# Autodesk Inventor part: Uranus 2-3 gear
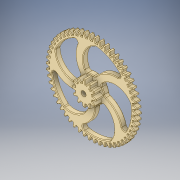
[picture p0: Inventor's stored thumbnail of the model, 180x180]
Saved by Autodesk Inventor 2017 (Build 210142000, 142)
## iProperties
Created: 2016-05
Part Number: Uranus 2-3 gear
Material: Generic
Document SubType Name: Modeling
Designer: Stan
Density: 1 g/cm^3
Appearance: Beige
Author: Stan
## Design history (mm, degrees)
sketch "Sketch1"
  geometry: A1 r 22.031 centre (27.061, -43.068) between (6.813, -51.751) and (8.981, -55.658); A2 r 22.031 centre (27.061, -43.068) between (6.813, -51.751) and (8.981, -55.658); A3 r 22.031 centre (-16.399, -48.148) between (4.096, -56.229) and (5.305, -51.927); A4 r 22.031 centre (-16.399, -48.148) between (4.096, -56.229) and (5.305, -51.927); A5 r 22.031 centre (31.878, -39.636) between (12.775, -50.61) and (15.382, -54.239); A6 r 22.031 centre (31.878, -39.636) between (12.775, -50.61) and (15.382, -54.239); A7 r 22.031 centre (-10.699, -49.726) between (10.596, -55.373) and (11.298, -50.96); A8 r 22.031 centre (-10.699, -49.726) between (10.596, -55.373) and (11.298, -50.96); A9 r 22.031 centre (36.264, -35.667) between (18.564, -48.785) and (21.575, -52.086); A10 r 22.031 centre (36.264, -35.667) between (18.564, -48.785) and (21.575, -52.086); A11 r 22.031 centre (-4.853, -50.632) between (16.953, -53.768) and (17.137, -49.304); A12 r 22.031 centre (-4.853, -50.632) between (16.953, -53.768) and (17.137, -49.304); A13 r 22.031 centre (40.159, -31.216) between (24.102, -46.3) and (27.476, -49.229); A14 r 22.031 centre (40.159, -31.216) between (24.102, -46.3) and (27.476, -49.229); A15 r 22.031 centre (1.057, -50.853) between (23.081, -51.437) and (22.745, -46.981); A16 r 22.031 centre (1.057, -50.853) between (23.081, -51.437) and (22.745, -46.981); A17 r 22.031 centre (43.512, -26.342) between (29.314, -43.189) and (33.005, -45.707); A18 r 22.031 centre (43.512, -26.342) between (29.314, -43.189) and (33.005, -45.707); A19 r 22.031 centre (6.954, -50.387) between (28.896, -48.409) and (28.046, -44.023); A20 r 22.031 centre (6.954, -50.387) between (28.896, -48.409) and (28.046, -44.023); A21 r 22.031 centre (46.275, -21.113) between (34.13, -39.493) and (38.088, -41.566); A22 r 22.031 centre (46.275, -21.113) between (34.13, -39.493) and (38.088, -41.566); A23 r 22.031 centre (12.757, -49.239) between (34.321, -44.727) and (32.967, -40.469); A24 r 22.031 centre (12.757, -49.239) between (34.321, -44.727) and (32.967, -40.469); A25 r 22.031 centre (48.414, -15.598) between (38.484, -35.264) and (42.656, -36.863); A26 r 22.031 centre (48.414, -15.598) between (38.484, -35.264) and (42.656, -36.863); A27 r 22.031 centre (18.387, -47.425) between (39.281, -40.441) and (37.442, -36.369); A28 r 22.031 centre (18.387, -47.425) between (39.281, -40.441) and (37.442, -36.369); A29 r 22.031 centre (49.897, -9.872) between (42.318, -30.558) and (46.647, -31.662); A30 r 22.031 centre (49.897, -9.872) between (42.318, -30.558) and (46.647, -31.662); A31 r 22.031 centre (23.768, -44.97) between (43.71, -35.607) and (41.411, -31.776); A32 r 22.031 centre (23.768, -44.97) between (43.71, -35.607) and (41.411, -31.776); A33 r 22.031 centre (50.706, -4.013) between (45.579, -25.439) and (50.008, -26.032); A34 r 22.031 centre (50.706, -4.013) between (45.579, -25.439) and (50.008, -26.032); A35 r 22.031 centre (28.828, -41.906) between (47.548, -30.292) and (44.82, -26.753); A36 r 22.031 centre (28.828, -41.906) between (47.548, -30.292) and (44.82, -26.753); A37 r 22.031 centre (50.829, 1.901) between (48.224, -19.975) and (52.692, -20.051); A38 r 22.031 centre (50.829, 1.901) between (48.224, -19.975) and (52.692, -20.051); A39 r 22.031 centre (33.498, -38.276) between (50.744, -24.567) and (47.623, -21.369); A40 r 22.031 centre (33.498, -38.276) between (50.744, -24.567) and (47.623, -21.369); A41 r 22.031 centre (50.264, 7.789) between (50.217, -14.242) and (54.663, -13.798); A42 r 22.031 centre (50.264, 7.789) between (50.217, -14.242) and (54.663, -13.798); A43 r 22.031 centre (37.715, -34.128) between (53.252, -18.51) and (49.782, -15.696); A44 r 22.031 centre (37.715, -34.128) between (53.252, -18.51) and (49.782, -15.696); A45 r 22.031 centre (49.02, 13.572) between (51.531, -8.315) and (55.895, -7.359); A46 r 22.031 centre (49.02, 13.572) between (51.531, -8.315) and (55.895, -7.359); A47 r 22.031 centre (41.422, -29.519) between (55.041, -12.202) and (51.267, -9.811); A48 r 22.031 centre (41.422, -29.519) between (55.041, -12.202) and (51.267, -9.811); A49 r 22.031 centre (47.113, 19.171) between (52.148, -2.277) and (56.372, -0.82); A50 r 22.031 centre (47.113, 19.171) between (52.148, -2.277) and (56.372, -0.82); A51 r 22.031 centre (44.569, -24.511) between (56.086, -5.73) and (52.06, -3.793); A52 r 22.031 centre (44.569, -24.511) between (56.086, -5.73) and (52.06, -3.793); A53 r 22.031 centre (44.569, 24.511) between (52.06, 3.793) and (56.086, 5.73); A54 r 22.031 centre (44.569, 24.511) between (52.06, 3.793) and (56.086, 5.73); A55 r 22.031 centre (47.113, -19.171) between (56.372, 0.82) and (52.148, 2.277); A56 r 22.031 centre (47.113, -19.171) between (56.372, 0.82) and (52.148, 2.277); A57 r 22.031 centre (41.422, 29.519) between (51.267, 9.811) and (55.041, 12.202); A58 r 22.031 centre (41.422, 29.519) between (51.267, 9.811) and (55.041, 12.202); A59 r 22.031 centre (49.02, -13.572) between (55.895, 7.359) and (51.531, 8.315); A60 r 22.031 centre (49.02, -13.572) between (55.895, 7.359) and (51.531, 8.315); A61 r 22.031 centre (37.715, 34.128) between (49.782, 15.696) and (53.252, 18.51); A62 r 22.031 centre (37.715, 34.128) between (49.782, 15.696) and (53.252, 18.51); A63 r 22.031 centre (50.264, -7.789) between (54.663, 13.798) and (50.217, 14.242); A64 r 22.031 centre (50.264, -7.789) between (54.663, 13.798) and (50.217, 14.242)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; 1 further point
  constraints: 864 point on circle, 432 centre point, 8 horizontal alignment, 8 vertical alignment, 1280 other
extrude "Extrusion1" new body sketch "Sketch1" distance "d0" = 6.35; taper "d1" = 0 deg
sketch "Sketch3"
  geometry: A1 r 10.7 centre (-12.898, -2.415) between (-8.219, 7.208) and (-12.381, 8.273); A2 r 10.7 centre (-12.898, -2.415) between (-8.219, 7.208) and (-12.381, 8.273); A3 r 10.7 centre (2.415, 12.898) between (-8.273, 12.381) and (-7.208, 8.219); A4 r 10.7 centre (2.415, 12.898) between (-8.273, 12.381) and (-7.208, 8.219); A5 r 10.7 centre (-9.963, -8.541) between (-10.722, 2.133) and (-14.859, 0.974); A6 r 10.7 centre (-9.963, -8.541) between (-10.722, 2.133) and (-14.859, 0.974); A7 r 10.7 centre (-4.358, 12.378) between (-13.355, 6.586) and (-10.352, 3.514); A8 r 10.7 centre (-4.358, 12.378) between (-13.355, 6.586) and (-10.352, 3.514); A9 r 10.7 centre (-4.358, -12.378) between (-10.352, -3.514) and (-13.355, -6.586); A10 r 10.7 centre (-4.358, -12.378) between (-10.352, -3.514) and (-13.355, -6.586); A11 r 10.7 centre (-9.963, 8.541) between (-14.859, -0.974) and (-10.722, -2.133); A12 r 10.7 centre (-9.963, 8.541) between (-14.859, -0.974) and (-10.722, -2.133); A13 r 10.7 centre (2.415, -12.898) between (-7.208, -8.219) and (-8.273, -12.381); A14 r 10.7 centre (2.415, -12.898) between (-7.208, -8.219) and (-8.273, -12.381); A15 r 10.7 centre (-12.898, 2.415) between (-12.381, -8.273) and (-8.219, -7.208); A16 r 10.7 centre (-12.898, 2.415) between (-12.381, -8.273) and (-8.219, -7.208); A17 r 10.7 centre (8.541, -9.963) between (-2.133, -10.722) and (-0.974, -14.859); A18 r 10.7 centre (8.541, -9.963) between (-2.133, -10.722) and (-0.974, -14.859); A19 r 10.7 centre (-12.378, -4.358) between (-6.586, -13.355) and (-3.514, -10.352); A20 r 10.7 centre (-12.378, -4.358) between (-6.586, -13.355) and (-3.514, -10.352); A21 r 10.7 centre (12.378, -4.358) between (3.514, -10.352) and (6.586, -13.355); A22 r 10.7 centre (12.378, -4.358) between (3.514, -10.352) and (6.586, -13.355); A23 r 10.7 centre (-8.541, -9.963) between (0.974, -14.859) and (2.133, -10.722); A24 r 10.7 centre (-8.541, -9.963) between (0.974, -14.859) and (2.133, -10.722); A25 r 10.7 centre (12.898, 2.415) between (8.219, -7.208) and (12.381, -8.273); A26 r 10.7 centre (12.898, 2.415) between (8.219, -7.208) and (12.381, -8.273); A27 r 10.7 centre (-2.415, -12.898) between (8.273, -12.381) and (7.208, -8.219); A28 r 10.7 centre (-2.415, -12.898) between (8.273, -12.381) and (7.208, -8.219); A29 r 10.7 centre (9.963, 8.541) between (10.722, -2.133) and (14.859, -0.974); A30 r 10.7 centre (9.963, 8.541) between (10.722, -2.133) and (14.859, -0.974); A31 r 10.7 centre (4.358, -12.378) between (13.355, -6.586) and (10.352, -3.514); A32 r 10.7 centre (4.358, -12.378) between (13.355, -6.586) and (10.352, -3.514); A33 r 10.7 centre (4.358, 12.378) between (10.352, 3.514) and (13.355, 6.586); A34 r 10.7 centre (4.358, 12.378) between (10.352, 3.514) and (13.355, 6.586); A35 r 10.7 centre (9.963, -8.541) between (14.859, 0.974) and (10.722, 2.133); A36 r 10.7 centre (9.963, -8.541) between (14.859, 0.974) and (10.722, 2.133); A37 r 10.7 centre (-2.415, 12.898) between (7.208, 8.219) and (8.273, 12.381); A38 r 10.7 centre (-2.415, 12.898) between (7.208, 8.219) and (8.273, 12.381); A39 r 10.7 centre (12.898, -2.415) between (12.381, 8.273) and (8.219, 7.208); A40 r 10.7 centre (12.898, -2.415) between (12.381, 8.273) and (8.219, 7.208); A41 r 10.7 centre (-8.541, 9.963) between (2.133, 10.722) and (0.974, 14.859); A42 r 10.7 centre (-8.541, 9.963) between (2.133, 10.722) and (0.974, 14.859); A43 r 10.7 centre (12.378, 4.358) between (6.586, 13.355) and (3.514, 10.352); A44 r 10.7 centre (12.378, 4.358) between (6.586, 13.355) and (3.514, 10.352); A45 r 10.7 centre (2.415, 12.898) between (-8.273, 12.381) and (-7.208, 8.219); A46 r 10.7 centre (-12.898, -2.415) between (-8.219, 7.208) and (-12.381, 8.273); A47 r 10.7 centre (-4.358, 12.378) between (-13.355, 6.586) and (-10.352, 3.514); A48 r 10.7 centre (-9.963, -8.541) between (-10.722, 2.133) and (-14.859, 0.974); A49 r 10.7 centre (-9.963, 8.541) between (-14.859, -0.974) and (-10.722, -2.133); A50 r 10.7 centre (-4.358, -12.378) between (-10.352, -3.514) and (-13.355, -6.586); A51 r 10.7 centre (-12.898, 2.415) between (-12.381, -8.273) and (-8.219, -7.208); A52 r 10.7 centre (2.415, -12.898) between (-7.208, -8.219) and (-8.273, -12.381); A53 r 10.7 centre (-12.378, -4.358) between (-6.586, -13.355) and (-3.514, -10.352); A54 r 10.7 centre (8.541, -9.963) between (-2.133, -10.722) and (-0.974, -14.859); A55 r 10.7 centre (-8.541, -9.963) between (0.974, -14.859) and (2.133, -10.722); A56 r 10.7 centre (12.378, -4.358) between (3.514, -10.352) and (6.586, -13.355); A57 r 10.7 centre (-2.415, -12.898) between (8.273, -12.381) and (7.208, -8.219); A58 r 10.7 centre (12.898, 2.415) between (8.219, -7.208) and (12.381, -8.273); A59 r 10.7 centre (4.358, -12.378) between (13.355, -6.586) and (10.352, -3.514); A60 r 10.7 centre (9.963, 8.541) between (10.722, -2.133) and (14.859, -0.974); A61 r 10.7 centre (9.963, -8.541) between (14.859, 0.974) and (10.722, 2.133); A62 r 10.7 centre (4.358, 12.378) between (10.352, 3.514) and (13.355, 6.586); A63 r 10.7 centre (12.898, -2.415) between (12.381, 8.273) and (8.219, 7.208); A64 r 10.7 centre (-2.415, 12.898) between (7.208, 8.219) and (8.273, 12.381)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; 1 further point
  constraints: 192 point on circle, 96 centre point, 8 horizontal alignment, 8 vertical alignment, 272 other
extrude "Extrusion3" join sketch "Sketch3" distance "d5" = 9.525; taper "d6" = 0 deg
sketch "Sketch4"
  geometry: C1 r 3.175 at (0, 0); 1 further point
  constraints: 1 centre point, 1 coincident
  dimensions: "d7" = 6.35 diameter of C1
extrude "Extrusion4" cut sketch "Sketch4" distance "d8" = 3.175; taper "d9" = 0 deg; dims "d14" = 15.875, "d15" = 0
sketch "Sketch5"
  geometry: A1 r 49.061 centre (0, 0) between (43.346, -22.98) and (48.333, 8.415); A2 r 49.061 centre (0, 0) between (35.25, 34.123) and (6.933, 48.568); A3 r 49.061 centre (0, 0) between (-21.56, 44.069) and (-44.049, 21.602); A4 r 49.061 centre (0, 0) between (-48.575, -6.887) and (-34.156, -35.218); A5 r 49.061 centre (0, 0) between (-8.461, -48.325) and (22.939, -43.367); A6 r 31.104 centre (11.604, 28.341) between (-17.222, 40.025) and (-14.123, 10.86); A7 r 22.848 centre (12.542, 26.708) between (5.506, 48.446) and (-8.121, 16.957); A8 r 31.104 centre (-23.368, 19.794) between (-43.388, -4.011) and (-14.693, -10.076); A9 r 22.848 centre (-21.526, 20.181) between (-44.373, 20.207) and (-18.637, -2.483); A10 r 31.104 centre (-26.046, -16.108) between (-9.593, -42.504) and (5.042, -17.087); A11 r 22.848 centre (-25.845, -14.236) between (-32.931, -35.957) and (-3.398, -18.492); A12 r 31.104 centre (7.271, -29.749) between (37.459, -22.258) and (17.809, -0.485); A13 r 22.848 centre (5.552, -28.979) between (24.021, -42.43) and (16.537, -8.946); A14 r 31.104 centre (30.54, -2.278) between (32.744, 28.748) and (5.965, 16.788); A15 r 22.848 centre (29.277, -3.674) between (47.776, 9.734) and (13.618, 12.963); A16 r 15.875 centre (0, 0) between (2.88, 15.612) and (-4.374, 15.26); A17 r 15.875 centre (0, 0) between (15.737, 2.085) and (13.162, 8.876); A18 r 15.875 centre (0, 0) between (6.846, -14.323) and (12.509, -9.775); A19 r 15.875 centre (0, 0) between (-13.957, 7.563) and (-15.865, 0.555); A20 r 15.875 centre (0, 0) between (-11.506, -10.937) and (-5.431, -14.917); A21 r 3.175 centre (-20.165, 41.217) between (-17.222, 40.025) and (-21.56, 44.069); A22 r 3.175 centre (-41.198, 20.204) between (-44.049, 21.602) and (-44.373, 20.207); A23 r 3.175 centre (-19.038, 0.666) between (-18.637, -2.483) and (-15.865, 0.555); A24 r 3.175 centre (-16.749, 9.076) between (-13.957, 7.563) and (-14.123, 10.86); A25 r 3.175 centre (-5.249, 18.312) between (-8.121, 16.957) and (-4.374, 15.26); A26 r 3.175 centre (3.456, 18.734) between (2.88, 15.612) and (5.965, 16.788); A27 r 3.175 centre (32.969, 31.915) between (32.744, 28.748) and (35.25, 34.123); A28 r 3.175 centre (6.484, 45.425) between (6.933, 48.568) and (5.506, 48.446); A29 r 3.175 centre (45.206, 7.87) between (48.333, 8.415) and (47.776, 9.734); A30 r 3.175 centre (15.794, 10.651) between (13.618, 12.963) and (13.162, 8.876); A31 r 3.175 centre (18.885, 2.502) between (15.737, 2.085) and (17.809, -0.485); A32 r 3.175 centre (40.541, -21.493) between (37.459, -22.258) and (43.346, -22.98); A33 r 3.175 centre (21.455, -40.561) between (22.939, -43.367) and (24.021, -42.43); A34 r 3.175 centre (-7.913, -45.198) between (-9.593, -42.504) and (-8.461, -48.325); A35 r 3.175 centre (8.215, -17.187) between (6.846, -14.323) and (5.042, -17.087); A36 r 3.175 centre (15.011, -11.73) between (16.537, -8.946) and (12.509, -9.775); A37 r 3.175 centre (-6.517, -17.901) between (-3.398, -18.492) and (-5.431, -14.917); A38 r 3.175 centre (-13.808, -13.125) between (-11.506, -10.937) and (-14.693, -10.076); A39 r 3.175 centre (-45.431, -6.441) between (-43.388, -4.011) and (-48.575, -6.887); A40 r 3.175 centre (-31.946, -32.938) between (-34.156, -35.218) and (-32.931, -35.957); 1 further point
  constraints: 80 point on circle, 40 centre point, 40 tangent, 19 equal radius
  dimensions: "d13" = 3.175 radius of A21 (derived)
extrude "Extrusion5" cut sketch "Sketch5" distance "d11" = 6.35; taper "d12" = 0 deg
fillet "Fillet1" dims "d16" = 0.79375
fillet "Fillet2" dims "d17" = 0.79375
fillet "Fillet3" dims "d18" = 0.79375
fillet "Fillet4" dims "d19" = 0.79375
fillet "Fillet5" dims "d20" = 0.79375
fillet "Fillet6" dims "d21" = 0.79375
fillet "Fillet7" dims "d22" = 0.79375
fillet "Fillet8" dims "d23" = 0.79375
fillet "Fillet9" dims "d24" = 0.79375
body "Solid1"
